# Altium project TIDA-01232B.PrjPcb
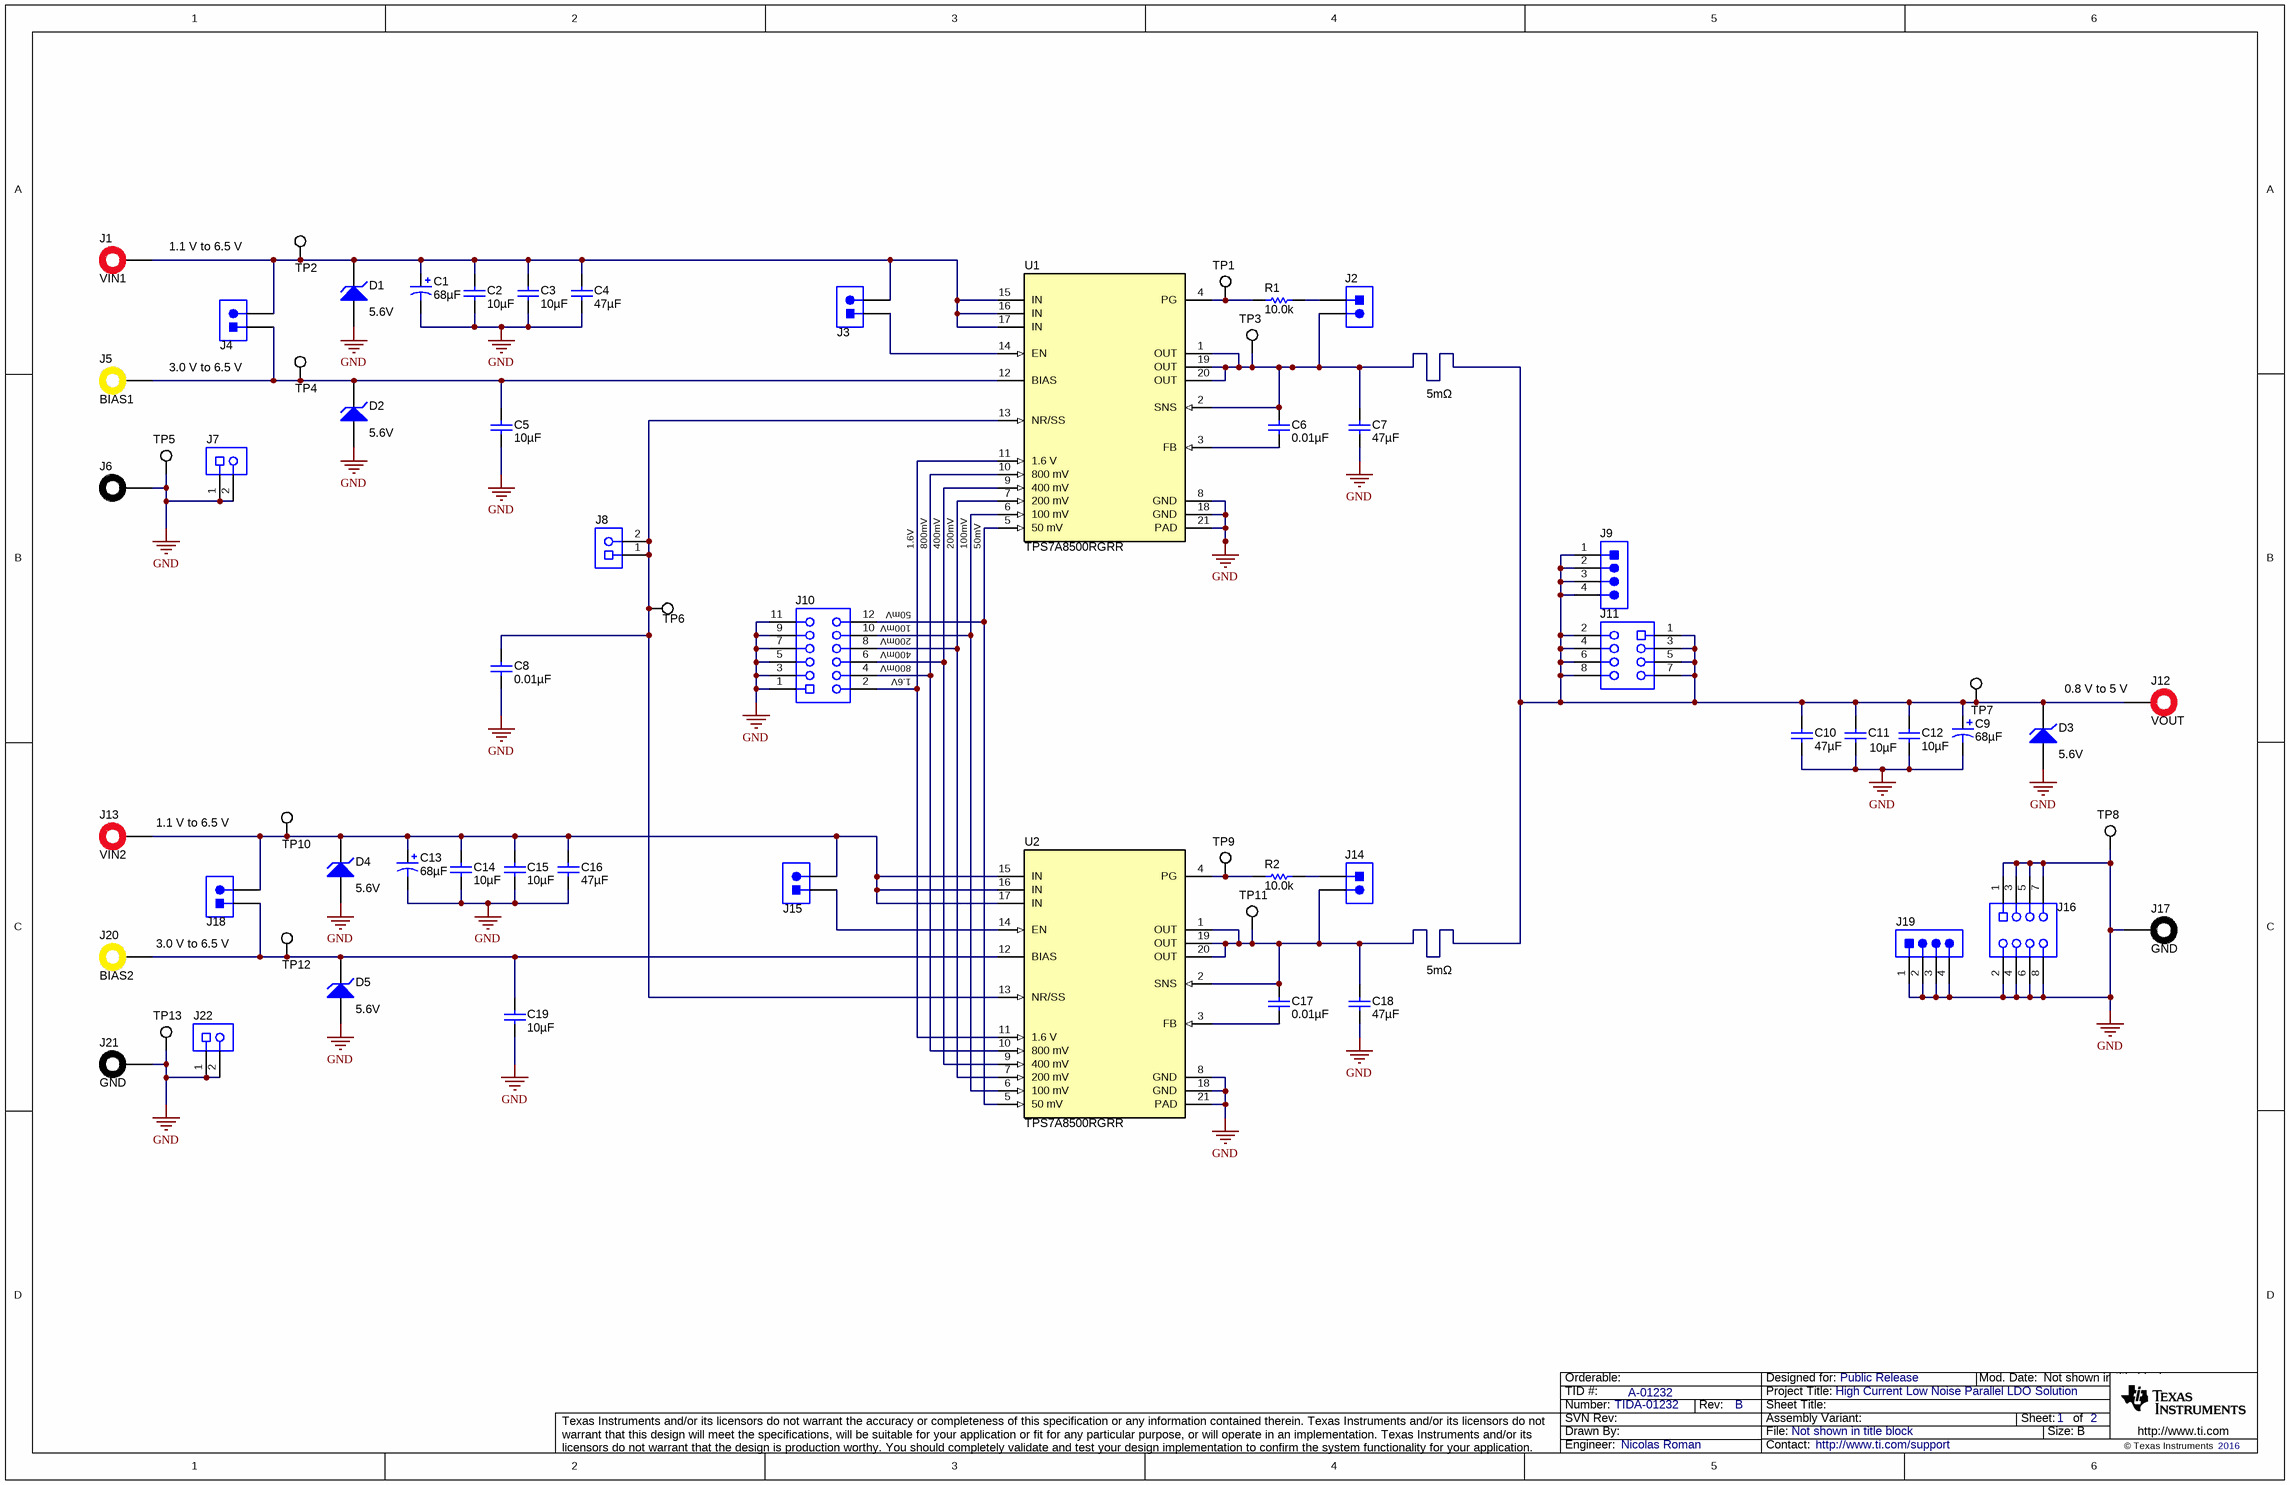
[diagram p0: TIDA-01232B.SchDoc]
CopyrightYear: 2016; PCB_Layout: Nicolas Roman; PCB_Rev: B; PRJ_Customer: Public Release; PRJ_Engineer: Nicolas Roman; PRJ_Number: TIDA-01232; PRJ_Title: High Current Low Noise Parallel LDO Solution; SCH_Rev: B; TechSupport: http://www.ti.com/support; TID: A-01232
2 sheets, 79 parts. Net scope: global (net labels, ports and power ports of the same name join across sheets).
Board file: TIDA-01232B.PcbDoc
Sheets:
  TIDA-01232B.SchDoc
  TIDA-01232B_Hardware.SchDoc

## Sheet TIDA-01232B.SchDoc
size 431 x 279 mm; Date: Not shown in title block; ApprovedBy: Not shown in title block; CheckedBy: Not shown in title block; Author: Not shown in title block; CompanyName: Not shown in title block; Engineer: Not shown in title block; Organization: Not shown in title block; Address1: Not shown in title block; Address2: Not shown in title block; Address3: Not shown in title block; Address4: Not shown in title block; DocumentNumber: 1; Revision: Use project parameter SCH_Rev; SheetNumber: 1; SheetTotal: 2; PageSetup: Record=PageOptions¦CenterHorizontal=True¦CenterVertical=True¦PrintScale=0.64¦XCorrection=1.00¦YCorrection=1.00¦PrintKind=2¦BorderSize=5000000¦LeftOffset=0¦BottomOffset=0¦Orientation=2¦PaperLength=1000¦PaperWidth=1000¦Scale=100¦PaperSource=15¦PrintQuality=-3¦MediaType=1¦DitherType=10¦PrintScaleMode=1¦PaperKind=Letter¦PaperIndex=1

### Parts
C1  ValueDisplayed: 68µF  [6032-28]  (hidden comment: TPSC686K016R0200)
C2  ValueDisplayed: 10µF  [0805_HV]  (hidden comment: GRM21BR61C106KE15L)
C3  ValueDisplayed: 10µF  [0805_HV]  (hidden comment: GRM21BR61C106KE15L)
C4  ValueDisplayed: 47µF  [0805_HV]  (hidden comment: GRM219R60G476ME44D)
C5  ValueDisplayed: 10µF  [0805_HV]  (hidden comment: GRM21BR61C106KE15L)
C6  ValueDisplayed: 0.01µF  [0603]  (hidden comment: GRM188R71H103KA01D)
C7  ValueDisplayed: 47µF  [0805_HV]  (hidden comment: GRM219R60G476ME44D)
C8  ValueDisplayed: 0.01µF  [0603]  (hidden comment: GRM188R71H103KA01D)
C9  ValueDisplayed: 68µF  [6032-28]  (hidden comment: TPSC686K016R0200)
C10  ValueDisplayed: 47µF  [0805_HV]  (hidden comment: GRM219R60G476ME44D)
C11  ValueDisplayed: 10µF  [0805_HV]  (hidden comment: GRM21BR61C106KE15L)
C12  ValueDisplayed: 10µF  [0805_HV]  (hidden comment: GRM21BR61C106KE15L)
C13  ValueDisplayed: 68µF  [6032-28]  (hidden comment: TPSC686K016R0200)
C14  ValueDisplayed: 10µF  [0805_HV]  (hidden comment: GRM21BR61C106KE15L)
C15  ValueDisplayed: 10µF  [0805_HV]  (hidden comment: GRM21BR61C106KE15L)
C16  ValueDisplayed: 47µF  [0805_HV]  (hidden comment: GRM219R60G476ME44D)
C17  ValueDisplayed: 0.01µF  [0603]  (hidden comment: GRM188R71H103KA01D)
C18  ValueDisplayed: 47µF  [0805_HV]  (hidden comment: GRM219R60G476ME44D)
C19  ValueDisplayed: 10µF  [0805_HV]  (hidden comment: GRM21BR61C106KE15L)
D1  value 5.6V  [SMA]  (hidden comment: SMAZ5V6-13-F)
D2  value 5.6V  [SMA]  (hidden comment: SMAZ5V6-13-F)
D3  value 5.6V  [SMA]  (hidden comment: SMAZ5V6-13-F)
D4  value 5.6V  [SMA]  (hidden comment: SMAZ5V6-13-F)
D5  value 5.6V  [SMA]  (hidden comment: SMAZ5V6-13-F)
J1  VIN1  [6091]
J2  PG1  [Molex_87898-0204]  (value not drawn)
J3  EN1  [Molex_87898-0204]  (value not drawn)
J4  BIAS1  [Molex_87898-0204]  (value not drawn)
J5  BIAS1  [CONN_108-0907-001]
J6  GND  [6092]  (value not drawn)
J7  SSQ-102-03-G-S  [Samtec_SSQ-102-03-x-S]  (value not drawn)
J8  SSQ-102-03-G-S  [Samtec_SSQ-102-03-x-S]  (value not drawn)
J9  Vout  [Mill-Max_342-xx-104-00-591000]  (value not drawn)
J10  SSQ-106-03-G-D  [Samtec_SSQ-106-03-x-D]  (value not drawn)
J11  SSQ-104-03-G-D  [Samtec_SSQ-104-03-x-D]  (value not drawn)
J12  VOUT  [6091]
J13  VIN2  [6091]
J14  PG2  [Molex_87898-0204]  (value not drawn)
J15  EN2  [Molex_87898-0204]  (value not drawn)
J16  SSQ-104-03-G-D  [Samtec_SSQ-104-03-x-D]  (value not drawn)
J17  GND  [6092]
J18  BIAS2  [Molex_87898-0204]  (value not drawn)
J19  GND  [Mill-Max_342-xx-104-00-591000]  (value not drawn)
J20  BIAS2  [CONN_108-0907-001]
J21  GND  [6092]
J22  SSQ-102-03-G-S  [Samtec_SSQ-102-03-x-S]  (value not drawn)
R1  ValueDisplayed: 10.0k  [0603]  (hidden comment: CRCW060310K0FKEA)
R2  ValueDisplayed: 10.0k  [0603]  (hidden comment: CRCW060310K0FKEA)
TP1  PG1  [Testpoint_Keystone_Compact]  (value not drawn)
TP2  VIN1  [Testpoint_Keystone_Compact]  (value not drawn)
TP3  VOUT1  [Testpoint_Keystone_Compact]  (value not drawn)
TP4  BIAS1  [Testpoint_Keystone_Compact]  (value not drawn)
TP5  GND  [Testpoint_Keystone_Compact]  (value not drawn)
TP6  NR/SS  [Testpoint_Keystone_Compact]  (value not drawn)
TP7  VOUT  [Testpoint_Keystone_Compact]  (value not drawn)
TP8  GND  [Testpoint_Keystone_Compact]  (value not drawn)
TP9  PG2  [Testpoint_Keystone_Compact]  (value not drawn)
TP10  VIN2  [Testpoint_Keystone_Compact]  (value not drawn)
TP11  VOUT2  [Testpoint_Keystone_Compact]  (value not drawn)
TP12  BIAS2  [Testpoint_Keystone_Compact]  (value not drawn)
TP13  GND  [Testpoint_Keystone_Compact]  (value not drawn)
U1  TPS7A8500RGRR  [RGR0020A]
U2  TPS7A8500RGRR  [RGR0020A]

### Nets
GND: C1.2(-) C2.2 C3.2 C4.2 C5.2 C7.2 C8.2 C9.2(-) C10.2 C11.2 C12.2 C13.2(-) C14.2 C15.2 C16.2 C18.2 C19.2 D1.2(A) D2.2(A) D3.2(A) D4.2(A) D5.2(A) J6.1 J7.1 J7.2 J10.1 J10.3 J10.5 J10.7 J10.9 J10.11 J16.1 J16.2 J16.3 J16.4 J16.5 J16.6 J16.7 J16.8 J17.1 J19.1 J19.2 J19.3 J19.4 J21.1 J22.1 J22.2 TP5.1 TP8.1 TP13.1 U1.8(GND) U1.18(GND) U1.21(PAD) U2.8(GND) U2.18(GND) U2.21(PAD)
NetC1_1: C1.1(+) C2.1 C3.1 C4.1 D1.1(K) J1.1 J3.2 J4.2 TP2.1 U1.15(IN) U1.16(IN) U1.17(IN)
NetC5_1: C5.1 D2.1(K) J4.1 J5.1 TP4.1 U1.12(BIAS)
NetC6_1: C6.1 U1.3(FB)
NetC6_2: C6.2 C7.1 C9.1(+) C10.1 C11.1 C12.1 C17.1 C18.1 D3.1(K) J2.2 J9.1 J9.2 J9.3 J9.4 J11.1 J11.2 J11.3 J11.4 J11.5 J11.6 J11.7 J11.8 J12.1 J14.2 TP3.1 TP7.1 TP11.1 U1.1(OUT) U1.2(SNS) U1.19(OUT) U1.20(OUT) U2.1(OUT) U2.2(SNS) U2.19(OUT) U2.20(OUT)
NetC8_1: C8.1 J8.1 J8.2 TP6.1 U1.13(NR/SS) U2.13(NR/SS)
NetC13_1: C13.1(+) C14.1 C15.1 C16.1 D4.1(K) J13.1 J15.2 J18.2 TP10.1 U2.15(IN) U2.16(IN) U2.17(IN)
NetC17_2: C17.2 U2.3(FB)
NetC19_1: C19.1 D5.1(K) J18.1 J20.1 TP12.1 U2.12(BIAS)
NetJ2_1: J2.1 R1.2
NetJ3_1: J3.1 U1.14(EN)
NetJ10_2: J10.2 U1.11(1.6_V) U2.11(1.6_V)
NetJ10_4: J10.4 U1.10(800_mV) U2.10(800_mV)
NetJ10_6: J10.6 U1.9(400_mV) U2.9(400_mV)
NetJ10_8: J10.8 U1.7(200_mV) U2.7(200_mV)
NetJ10_10: J10.10 U1.6(100_mV) U2.6(100_mV)
NetJ10_12: J10.12 U1.5(50_mV) U2.5(50_mV)
NetJ14_1: J14.1 R2.2
NetJ15_1: J15.1 U2.14(EN)
NetR1_1: R1.1 TP1.1 U1.4(PG)
NetR2_1: R2.1 TP9.1 U2.4(PG)

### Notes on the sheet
- 1.1 V to 6.5 V
- 3.0 V to 6.5 V
- 5mΩ
- 1.6V
- 800mV
- 400mV
- 200mV
- 100mV
- (near U1) 50mV
- (near J10) 100mV
- (near J10) 50mV
- (near J10) 1.6V
- (near J10) 800mV
- (near J10) 400mV
- (near J10) 200mV
- (near J12) 0.8 V to 5 V
- (near J13) 1.1 V to 6.5 V

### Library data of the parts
C1 C13 = TPSC686K016R0200: CAP, TA, 68 µF, 16 V, +/- 10%, 0.2 ohm, SMD; Manufacturer: AVX; Polarized: Y; CompType: Capacitor; Value: 68uF; U/M: EA; Cap_F: 0.000068; Tolerance_%: 10; ESR_ohm: 0.2; Value1: 0.2 ohm; VDC_V: 16; Value2: 16V; IRMS_A: 0.667; TaMin_C: -55; TaMax_C: 125; Cap_Case: C
C2 C3 C5 C11 C12 C14 C15 C19 = GRM21BR61C106KE15L: CAP, CERM, 10 µF, 16 V, +/- 10%, X5R, 0805; Manufacturer: MuRata; Polarized: N; CompType: Capacitor; Value: 10uF; U/M: EA; Cap_F: 0.00001; Tolerance_%: 10; ESR_ohm: 0.008; Value1: 0.008 ohm; VDC_V: 16; Value2: 16V; TaMin_C: -55; TaMax_C: 85; Cap_Case: 0805; AEC Category: Q200
C4 C7 C10 C16 C18 = GRM219R60G476ME44D: CAP, CERM, 47 µF, 4 V, +/- 20%, X5R, 0805; Manufacturer: MuRata; Polarized: N; CompType: Capacitor; Value: 47uF; U/M: EA; Cap_F: 0.000047; Tolerance_%: 20; Value1: Unknown; VDC_V: 4; Value2: 4V; TaMin_C: -55; TaMax_C: 85; Cap_Case: 0805; AEC Category: Q200
C6 C8 C17 = GRM188R71H103KA01D: CAP, CERM, 0.01 µF, 50 V, +/- 10%, X7R, 0603; Manufacturer: MuRata; Polarized: N; CompType: Capacitor; Value: 0.01uF; U/M: EA; Cap_F: 0.00000001; Tolerance_%: 10; Value1: Unknown; VDC_V: 50; Value2: 50V; TaMin_C: -55; TaMax_C: 125; AEC Category: Q200
C9 = TPSC686K016R0200: CAP, TA, 68 µF, 16 V, +/- 10%, 0.2 ohm, SMD; Manufacturer: AVX; Polarized: Y; CompType: Capacitor; Value: 68uF; U/M: EA; Cap_F: 0.000068; Tolerance_%: 10; Value1: 0.2 ohm; VDC_V: 16; Value2: 16V; ESR_ohm: 0.2; IRMS_A: 0.667; TaMin_C: -55; TaMax_C: 125; Cap_Case: C; AEC Category: Q200
D1-D5 = SMAZ5V6-13-F: Diode, Zener, 5.6 V, 1 W, SMA; Manufacturer: Diodes Inc.; SymbolCreator: a0412235; U/M: EA; Power_W: 1; Vz_V: 5.6; Value1: 1W; RJA_CperW: 125; SizeAreaWB_mm2: 37.3428; SizeArea_mm2: 16.3228; SizeX_mm: 5.59; SizeY_mm: 2.92; SizeZ_mm: 2.87; AEC Category: Q101; AEC Qualified: N
J1 J12 J13 = 6091: Standard Banana Jack, Insulated, Red; Manufacturer: Keystone; SymbolCreator: a0412235; CompType: Connector; U/M: EA
J2-J4 J14 J15 J18 = 87898-0204: Header, 2.54 mm, 2x1, Gold, R/A, SMT; Manufacturer: Molex; SymbolCreator: a0412235; U/M: EA
J5 J20 = 108-0907-001: BANANA JACK, 15A, Insulated, Nylon,Yellow; Manufacturer: Emerson Network Power; SymbolCreator: a0799721; CompType: Connector; U/M: EA
J6 J17 J21 = 6092: Standard Banana Jack, Insulated, Black; Manufacturer: Keystone; SymbolCreator: a0412235; CompType: Connector; U/M: EA
J7 J8 J22 = SSQ-102-03-G-S: Receptacle, 2.54mm, 2x1, Gold, TH; Manufacturer: Samtec; SymbolCreator: a0412235; Pitch_mm: 2.54; Gender: Female; Row_Count: 1; Current_A: 6.3; Cert_CSA: Y
J9 J19 = 342-10-104-00-591000: Header, 100mil, 4x1, Gold, TH; Manufacturer: Mill-Max; SymbolCreator: a0412235
J10 = SSQ-106-03-G-D: Receptacle, 2.54mm, 6x2, Gold, TH; Manufacturer: Samtec; SymbolCreator: a0412235; Pitch_mm: 2.54; Gender: Female; Row_Count: 2; Current_A: 6.3; Cert_CSA: Y
J11 J16 = SSQ-104-03-G-D: Receptacle, 2.54mm, 4x2, Gold, TH; Manufacturer: Samtec; SymbolCreator: a0412235; Pitch_mm: 2.54; Gender: Female; Row_Count: 2; Current_A: 6.3; Cert_CSA: Y
R1 R2 = CRCW060310K0FKEA: RES, 10.0 k, 1%, 0.1 W, 0603; Manufacturer: Vishay-Dale; CompType: Resistor; Value: 10.0k; Res_ohm: 10000; Value_Code: 10k0; Tolerance_%: 1; Power_W: 0.1; Value2: 0.1W; VDC_V: 75; TempCo: 100 ppm/C; EIA_Code: E96; U/M: EA
TP1-TP13 = 5016: Test Point, Compact, SMT; Manufacturer: Keystone; CompType: Test Point Loop; U/M: EA
U1 U2 = TPS7A8500RGRR: 4-A, 6-μVRMS, RF, LDO Voltage Regulator, RGR0020A; Alternate PartNumber: TPS7A8500RGRT; Manufacturer: Texas Instruments; SymbolCreator: a0411947; CompType: IC; U/M: EA

## Sheet TIDA-01232B_Hardware.SchDoc
size 431 x 279 mm; Date: Not shown in title block; ApprovedBy: Not shown in title block; CheckedBy: Not shown in title block; Author: Not shown in title block; CompanyName: Not shown in title block; Engineer: Not shown in title block; Organization: Not shown in title block; Address1: Not shown in title block; Address2: Not shown in title block; Address3: Not shown in title block; Address4: Not shown in title block; DocumentNumber: 1; Revision: Use project parameter SCH_Rev; SheetNumber: 2; SheetTotal: 2; PageSetup: Record=PageOptions¦CenterHorizontal=True¦CenterVertical=True¦PrintScale=1.00¦XCorrection=1.00¦YCorrection=1.00¦PrintKind=0¦BorderSize=5000000¦LeftOffset=0¦BottomOffset=0¦Orientation=2¦PaperLength=1000¦PaperWidth=1000¦Scale=100¦PaperSource=15¦PrintQuality=600¦MediaType=1¦DitherType=10¦PaperKind=Letter¦PrintScaleMode=1
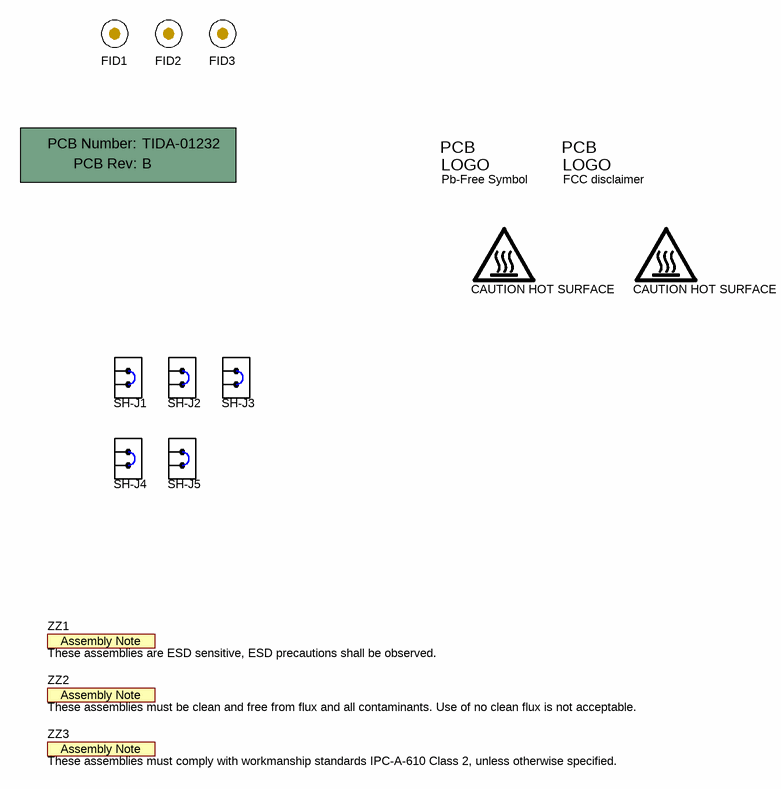
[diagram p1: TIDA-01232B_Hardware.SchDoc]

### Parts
!PCB1  Printed Circuit Board  (value not drawn)  (mechanical)
FID1  Fiducial  [Fiducial10-30]  (value not drawn)
FID2  Fiducial  [Fiducial10-30]  (value not drawn)
FID3  Fiducial  [Fiducial10-30]  (value not drawn)
Logo2  Pb-Free Symbol  [Pb-Free_Overlay_Small]  (no BOM)
Logo3  FCC disclaimer  [FCC_disclaimer_stacked]  (no BOM)
LOGO5  CAUTION HOT SURFACE  [IEC_HotSurface_Small]  (no BOM)
LOGO6  CAUTION HOT SURFACE  [IEC_HotSurface_Small]  (no BOM)
SH-J1  969102-0000-DA  [SNT-100-BK-G]  (value not drawn)
SH-J2  969102-0000-DA  [SNT-100-BK-G]  (value not drawn)
SH-J3  969102-0000-DA  [SNT-100-BK-G]  (value not drawn)
SH-J4  969102-0000-DA  [SNT-100-BK-G]  (value not drawn)
SH-J5  969102-0000-DA  [SNT-100-BK-G]  (value not drawn)
ZZ1  These assemblies are ESD sensitive, ESD precautions shall be observed.  [AssemblyNote]  (no BOM)
ZZ2  These assemblies must be clean and free from flux and all contaminants. Use of no clean flux is not acceptable.  [AssemblyNote]  (no BOM)
ZZ3  These assemblies must comply with workmanship standards IPC-A-610 Class 2, unless otherwise specified.  [AssemblyNote]  (no BOM)

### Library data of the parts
!PCB1 = PCB: Manufacturer: Any; PartNumber: TIDA-01232; SymbolCreator: a0412235
FID1-FID3 = Fiducial: Fiducial mark.  There is nothing to buy or mount.; SymbolCreator: codlsc
Logo2 = Pb-Free: SymbolCreator: a0412235
Logo3 = FCC_disclaimer: SymbolCreator: codlsc
LOGO5 LOGO6 = IEC_HotSurface: IEC 61010-1 Hot Surface Warning; SymbolCreator: a0412235
SH-J1-SH-J5 = 969102-0000-DA: Shunt, 100mil, Gold plated, Black; Manufacturer: 3M; Alternate Manufacturer: Samtec; Value: 1x2; Note: You can "mate" this to a header by matching the designator.  i.e. use SH-J3 for header J3
ZZ1-ZZ3 = AssemblyNote: SymbolCreator: codlsc

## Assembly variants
001: not fitted !PCB1 C1 C9 C13 FID1 FID2 FID3 J2 J9 J14 J19 Logo2 Logo3 LOGO4 LOGO5 LOGO6 R1 R2 SH-J1 SH-J2 SH-J3 SH-J4 SH-J5 TP1 TP9 ZZ1 ZZ2 ZZ3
